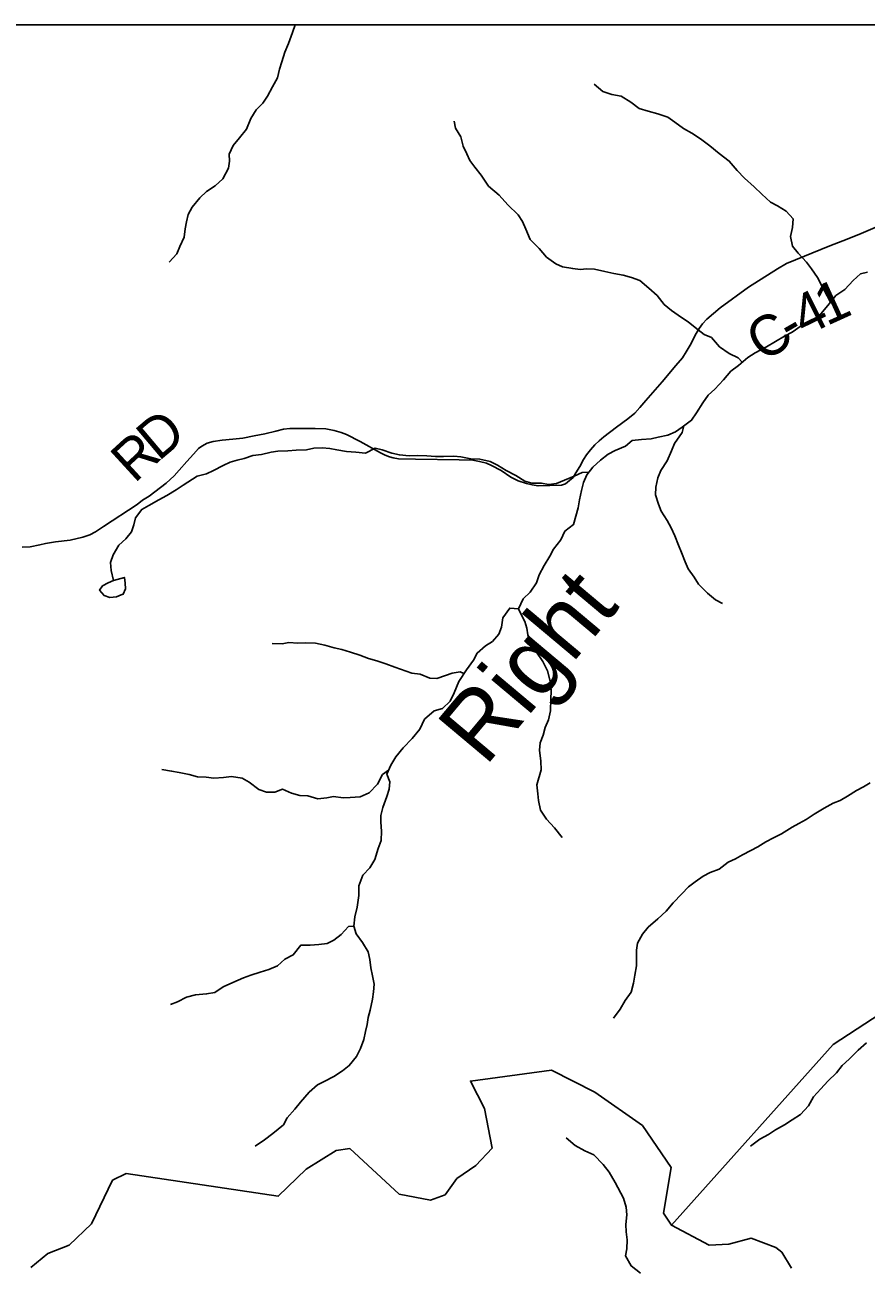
# Model space of a CAD drawing. Extents: x 0 to 34, y 0 to 22.
# Drawn here: x 5.025 to 6.209, y 19.152 to 20.9 of the extents above; entities that cross this region are included whole.
import ezdxf

# ---------------------------------------------------------------- set-up
doc = ezdxf.new("R2010")
doc.units = 0
for name, color, linetype in [('Default', 7, 'Continuous'), ('GM_X_County_Road', 7, 'Continuous'), ('GM_X_County_Road_Text', 7, 'Continuous'), ('GM_X_Minor_Lake', 7, 'Continuous'), ('GM_X_Minor_River', 7, 'Continuous'), ('GM_X_Minor_River_Text', 7, 'Continuous'), ('SH_Cut_Line', 7, 'Continuous'), ('SH_Data', 7, 'Continuous')]:
    doc.layers.add(name, color=color, linetype=linetype)

msp = doc.modelspace()

# ---------------------------------------------------------------- linework, layer by layer
at = {"layer": 'Default'}
for points in [[(6.416, 20.9), (2.4845, 20.9)], [(8.9, 18.9397), (8.9, 20.9), (6.416, 20.9), (6.3907, 20.8258), (6.4542, 20.7247), (6.5744, 20.5412), (6.467, 20.1963), (6.4168, 20.1498), (6.3788, 19.8553), (6.4211, 19.7542), (6.3989, 19.6679), (6.4166, 19.6301), (6.1627, 19.4643), (5.935, 19.2098), (5.9881, 19.1818), (6.0158, 19.1833), (6.0473, 19.1917), (6.082, 19.1783), (6.0902, 19.1718), (6.104, 19.1492)], [(5.0333, 19.1501), (5.0571, 19.1699), (5.0871, 19.1817), (5.1189, 19.2117), (5.1485, 19.2732), (5.1675, 19.2824), (5.3815, 19.2505), (5.4209, 19.2887), (5.4629, 19.3148), (5.4823, 19.3176), (5.5519, 19.2533), (5.5958, 19.2452), (5.6163, 19.2525), (5.6329, 19.2758), (5.6596, 19.2941), (5.6826, 19.3181), (5.6719, 19.3741), (5.6519, 19.4127), (5.7661, 19.4283), (5.8271, 19.3972), (5.8943, 19.35), (5.9345, 19.291), (5.9239, 19.227), (5.935, 19.2098), (6.1627, 19.4643), (6.4166, 19.6301)], [(6.104, 19.1492), (6.0902, 19.1718), (6.082, 19.1783), (6.0473, 19.1917), (6.0158, 19.1833), (5.9881, 19.1818), (5.935, 19.2098), (5.9239, 19.227), (5.9345, 19.291), (5.8943, 19.35), (5.8271, 19.3972), (5.7661, 19.4283), (5.6519, 19.4127), (5.6719, 19.3741), (5.6826, 19.3181), (5.6596, 19.2941), (5.6329, 19.2758), (5.6163, 19.2525), (5.5958, 19.2452), (5.5519, 19.2533), (5.4823, 19.3176), (5.4629, 19.3148), (5.4209, 19.2887), (5.3815, 19.2505), (5.1675, 19.2824), (5.1485, 19.2732), (5.1189, 19.2117), (5.0871, 19.1817), (5.0571, 19.1699), (5.0333, 19.1501)]]:
    msp.add_lwpolyline(points, dxfattribs=at)
at = {"layer": 'GM_X_County_Road'}
msp.add_lwpolyline([(5.0212, 20.1644), (5.0322, 20.165), (5.0459, 20.168), (5.054, 20.1698), (5.068, 20.1721), (5.0886, 20.1746), (5.1067, 20.1784), (5.1163, 20.1817), (5.1242, 20.1863), (5.1354, 20.1937), (5.183, 20.2247), (5.1906, 20.2306), (5.2, 20.2362), (5.2239, 20.2547), (5.2351, 20.2652), (5.242, 20.273), (5.2527, 20.2853), (5.2621, 20.2957), (5.2692, 20.3033), (5.2738, 20.3066), (5.2814, 20.3109), (5.2898, 20.3135), (5.3025, 20.3153), (5.3175, 20.3165), (5.3315, 20.3181), (5.3475, 20.3211), (5.3625, 20.3239), (5.378, 20.328), (5.389, 20.3305), (5.3979, 20.3318), (5.4134, 20.3315), (5.4337, 20.3318), (5.4485, 20.331), (5.4604, 20.329), (5.4699, 20.3262), (5.4777, 20.3231), (5.4968, 20.3132), (5.5256, 20.2972), (5.5322, 20.2942), (5.538, 20.2919), (5.5431, 20.2903), (5.5507, 20.2891), (5.5749, 20.2883), (5.6364, 20.2875), (5.6553, 20.2868), (5.6649, 20.2853), (5.6748, 20.2827), (5.6817, 20.2797), (5.6952, 20.2723), (5.7087, 20.2631), (5.7193, 20.2578), (5.7308, 20.254), (5.7387, 20.2524), (5.7473, 20.2507), (5.7801, 20.2517), (5.786, 20.2537), (5.7913, 20.2585), (5.7964, 20.2624), (5.8005, 20.269), (5.8058, 20.2781), (5.8112, 20.288), (5.8155, 20.2947), (5.8211, 20.3018), (5.8272, 20.3086), (5.833, 20.3142), (5.8399, 20.3201), (5.8574, 20.3333), (5.8735, 20.345), (5.8834, 20.3534), (5.8905, 20.3613), (5.8989, 20.371), (5.922, 20.3974), (5.9411, 20.4203), (5.9503, 20.431), (5.9556, 20.4396), (5.9625, 20.4513), (5.9683, 20.463), (5.9739, 20.4722), (5.9788, 20.479), (5.9849, 20.4857), (6.0034, 20.5014), (6.0434, 20.5304), (6.0843, 20.5564), (6.097, 20.564), (6.1579, 20.5888), (6.1825, 20.5981), (6.2018, 20.6062), (6.2468, 20.6255)], dxfattribs=at)
at = {"layer": 'GM_X_Minor_Lake'}
for points in [[(5.1603, 20.0972), (5.1634, 20.0984), (5.1665, 20.106), (5.1662, 20.1139), (5.1651, 20.1219), (5.1499, 20.1175)], [(5.1499, 20.1175), (5.142, 20.1141), (5.1343, 20.11), (5.1301, 20.104), (5.1365, 20.0963), (5.1444, 20.0936), (5.1539, 20.0947), (5.1603, 20.0972)]]:
    msp.add_lwpolyline(points, dxfattribs=at)
at = {"layer": 'GM_X_Minor_River'}
for points in [[(5.4055, 20.9), (5.4014, 20.889), (5.396, 20.8738), (5.3909, 20.8614), (5.3867, 20.8477), (5.3832, 20.8375), (5.3804, 20.8254), (5.3735, 20.8126), (5.3666, 20.7994), (5.36, 20.7895), (5.3505, 20.7805), (5.3432, 20.7681), (5.337, 20.7533), (5.3271, 20.7409), (5.3183, 20.7303), (5.3125, 20.7179), (5.3128, 20.708), (5.3116, 20.6981), (5.3035, 20.683), (5.2928, 20.6732)], [(6.1588, 20.5096), (6.154, 20.5185), (6.1473, 20.5315), (6.1406, 20.5441), (6.132, 20.5563), (6.1249, 20.5658), (6.1132, 20.5784), (6.1054, 20.5884), (6.1024, 20.602), (6.1052, 20.6145), (6.1064, 20.6267), (6.0963, 20.6374), (6.0843, 20.6451), (6.0744, 20.6501), (6.0621, 20.6616), (6.0515, 20.6719), (6.0376, 20.6842), (6.0275, 20.6949), (6.0163, 20.7082), (6.0023, 20.719), (5.9888, 20.7297), (5.976, 20.7393), (5.9636, 20.7474), (5.9519, 20.7539), (5.9399, 20.7631), (5.9301, 20.77), (5.9157, 20.7747), (5.9021, 20.7782), (5.8897, 20.7821), (5.8776, 20.7913), (5.8641, 20.7994), (5.8512, 20.8018), (5.8384, 20.8061), (5.8263, 20.8164)], [(6.0346, 20.4249), (6.0287, 20.4312), (6.0162, 20.4373), (6.0027, 20.4466), (5.9911, 20.4596), (5.9809, 20.4642), (5.9685, 20.4738), (5.9587, 20.4818), (5.9489, 20.488), (5.935, 20.4976), (5.9248, 20.506), (5.9147, 20.519), (5.9031, 20.5293), (5.8903, 20.5401), (5.8786, 20.5443), (5.8669, 20.5475), (5.854, 20.5499), (5.8412, 20.5526), (5.8268, 20.5558), (5.8158, 20.5562), (5.8063, 20.5556), (5.7961, 20.5568), (5.7818, 20.5592), (5.772, 20.5634), (5.7592, 20.573), (5.749, 20.5849), (5.7359, 20.5979), (5.73, 20.6123), (5.7255, 20.623), (5.7192, 20.6325), (5.7045, 20.6467), (5.6925, 20.6601), (5.6775, 20.6727), (5.667, 20.6884), (5.658, 20.6994), (5.6513, 20.709), (5.6468, 20.7185), (5.642, 20.7292), (5.6383, 20.7421), (5.6312, 20.7547), (5.629, 20.7642)], [(5.2928, 20.6732), (5.2806, 20.6654), (5.2711, 20.6564), (5.2604, 20.6432), (5.255, 20.633), (5.2526, 20.6227), (5.2506, 20.6129), (5.249, 20.6008), (5.2429, 20.5879), (5.2386, 20.5777), (5.2279, 20.5657)], [(6.2111, 20.5518), (6.2012, 20.5493), (6.1909, 20.5399), (6.1791, 20.5274), (6.1661, 20.5188), (6.155, 20.5049), (6.1451, 20.4932), (6.131, 20.4815), (6.1177, 20.476), (6.1047, 20.4673), (6.0941, 20.4614), (6.0815, 20.4543), (6.0686, 20.4468), (6.0526, 20.4382), (6.0423, 20.4318), (6.0293, 20.4202), (6.0187, 20.4123), (6.008, 20.4002), (5.9961, 20.3871), (5.9866, 20.3784), (5.9793, 20.3678), (5.9701, 20.3535), (5.9632, 20.3433), (5.9502, 20.3336), (5.9407, 20.3268), (5.9301, 20.3223), (5.9161, 20.3194), (5.9066, 20.3172), (5.8929, 20.3162), (5.8797, 20.3148), (5.8701, 20.3069), (5.8557, 20.3006), (5.8458, 20.2957), (5.8351, 20.2871), (5.8244, 20.2773), (5.816, 20.2664), (5.811, 20.2558), (5.8083, 20.2441), (5.8055, 20.2312), (5.8035, 20.2198), (5.8004, 20.2081), (5.7969, 20.1964), (5.7851, 20.187), (5.7793, 20.1749), (5.769, 20.1617), (5.7636, 20.1519), (5.7559, 20.1386), (5.749, 20.1254), (5.7451, 20.1141), (5.7363, 20.1012), (5.7263, 20.0918), (5.7198, 20.0779), (5.7073, 20.0787), (5.6977, 20.0651), (5.6957, 20.0519), (5.6922, 20.042), (5.6831, 20.0319), (5.6732, 20.0255), (5.6617, 20.0154), (5.6563, 20.0052), (5.6464, 19.992), (5.6356, 19.9754), (5.6291, 19.9595), (5.6237, 19.9478), (5.6126, 19.9372), (5.6012, 19.9343), (5.5875, 19.9223), (5.5806, 19.9083)], [(5.9526, 20.3353), (5.9502, 20.326), (5.9391, 20.3105), (5.9352, 20.3003), (5.929, 20.2863), (5.9198, 20.2727), (5.9156, 20.2621), (5.9132, 20.2489), (5.9127, 20.2383), (5.9168, 20.2253), (5.9205, 20.2154), (5.9291, 20.2021), (5.9347, 20.1918), (5.9399, 20.1804), (5.9451, 20.1674), (5.9491, 20.1572), (5.9543, 20.1438), (5.9584, 20.1339), (5.967, 20.1225), (5.973, 20.1126), (5.9858, 20.0999), (5.997, 20.0904), (6.0068, 20.085)], [(5.8188, 20.2699), (5.8092, 20.2695), (5.7982, 20.2646), (5.7842, 20.2591), (5.7731, 20.2542), (5.7622, 20.2528), (5.7516, 20.2548), (5.7383, 20.2545), (5.7285, 20.2576), (5.7161, 20.2653), (5.7025, 20.2723), (5.6901, 20.2799), (5.6799, 20.2853), (5.6652, 20.2885), (5.6527, 20.289), (5.6387, 20.2917), (5.6285, 20.2926), (5.6141, 20.2923), (5.6031, 20.292), (5.5906, 20.2929), (5.5781, 20.2934), (5.566, 20.2931), (5.552, 20.2944), (5.5414, 20.2971), (5.5278, 20.3014), (5.518, 20.3038), (5.5043, 20.2967), (5.4907, 20.2983), (5.4778, 20.2992), (5.4642, 20.3015), (5.454, 20.3035), (5.4434, 20.3044), (5.4317, 20.3037), (5.4211, 20.3015), (5.407, 20.3009), (5.3949, 20.3002), (5.3809, 20.2996), (5.3714, 20.2981), (5.3578, 20.2952), (5.346, 20.2938), (5.3335, 20.2893), (5.3236, 20.2871), (5.3138, 20.2842), (5.3039, 20.2797), (5.2906, 20.2726), (5.2807, 20.2678), (5.2674, 20.2645), (5.2476, 20.2517), (5.2381, 20.2454), (5.2248, 20.2375), (5.2137, 20.2311), (5.1993, 20.2233), (5.1894, 20.2177), (5.1806, 20.2056), (5.1782, 20.1958), (5.1751, 20.1859), (5.1671, 20.1761), (5.1572, 20.1675), (5.1491, 20.1535), (5.1456, 20.1429), (5.1466, 20.1315), (5.1499, 20.1175)], [(5.7198, 20.0779), (5.7235, 20.0695), (5.7287, 20.06), (5.7313, 20.0504), (5.7327, 20.041), (5.7361, 20.0303), (5.7439, 20.0181), (5.754, 20.0036), (5.7603, 19.9903), (5.7647, 19.9739), (5.7658, 19.9618), (5.7653, 19.9508), (5.7648, 19.9341), (5.762, 19.9212), (5.757, 19.9106), (5.7543, 19.8996), (5.75, 19.889), (5.7492, 19.8788), (5.7509, 19.8632), (5.7516, 19.8511), (5.7453, 19.8299), (5.7468, 19.8174), (5.7478, 19.8079), (5.7507, 19.7942), (5.7593, 19.7816), (5.7702, 19.7694), (5.7811, 19.7556)], [(5.6429, 19.9867), (5.6376, 19.989), (5.6263, 19.9872), (5.6168, 19.9839), (5.6046, 19.9794), (5.5948, 19.9803), (5.5812, 19.9857), (5.5695, 19.9873), (5.5457, 19.9955), (5.5332, 20.0001), (5.5204, 20.0044), (5.5087, 20.0079), (5.4962, 20.0126), (5.4834, 20.0168), (5.4709, 20.0204), (5.4604, 20.0227), (5.4471, 20.0266), (5.4339, 20.0294), (5.4195, 20.0299), (5.4093, 20.0292), (5.3964, 20.0301), (5.387, 20.0283), (5.3729, 20.0288)], [(5.5806, 19.9083), (5.5702, 19.8951), (5.5572, 19.8819), (5.5469, 19.8691), (5.54, 19.8574), (5.5342, 19.8449), (5.5387, 19.8343), (5.5378, 19.8236), (5.5343, 19.8134), (5.5289, 19.7979), (5.5261, 19.7866), (5.5257, 19.7771), (5.5271, 19.7646), (5.5266, 19.7513), (5.522, 19.7403), (5.5177, 19.7248), (5.5104, 19.7131), (5.5008, 19.7029), (5.495, 19.6878), (5.4949, 19.6741), (5.4925, 19.6575), (5.4894, 19.6438), (5.4877, 19.631), (5.4911, 19.6203), (5.5, 19.6077), (5.5083, 19.5947), (5.5104, 19.5841), (5.5119, 19.5723), (5.514, 19.5609), (5.5166, 19.5491), (5.5157, 19.5385), (5.5141, 19.5279), (5.511, 19.5128), (5.5079, 19.5025), (5.5066, 19.4923), (5.5043, 19.4825), (5.5019, 19.4715), (5.4973, 19.4586), (5.4919, 19.4473), (5.4815, 19.4345), (5.472, 19.427), (5.4598, 19.4191), (5.4461, 19.4124), (5.4366, 19.4075), (5.4252, 19.397), (5.413, 19.3831), (5.4049, 19.3733), (5.3942, 19.3608), (5.3888, 19.351), (5.374, 19.339), (5.3622, 19.33), (5.3492, 19.321)], [(5.5367, 19.8504), (5.5285, 19.8442), (5.5212, 19.831), (5.5094, 19.8186), (5.4968, 19.813), (5.4828, 19.812), (5.473, 19.8117), (5.4594, 19.8133), (5.4499, 19.8115), (5.4374, 19.8101), (5.423, 19.8144), (5.4117, 19.8148), (5.4003, 19.818), (5.3875, 19.8238), (5.3769, 19.8197), (5.3648, 19.8194), (5.3542, 19.8233), (5.3406, 19.8336), (5.3308, 19.8394), (5.3157, 19.8418), (5.3047, 19.8404), (5.2911, 19.8393), (5.2801, 19.8406), (5.268, 19.8411), (5.2563, 19.8442), (5.2419, 19.8473), (5.2314, 19.8493), (5.2177, 19.8517)], [(6.2148, 19.8325), (6.2053, 19.8269), (6.1955, 19.822), (6.1829, 19.8138), (6.1726, 19.8078), (6.1627, 19.8041), (6.1498, 19.797), (6.1357, 19.7887), (6.1247, 19.7812), (6.1144, 19.7753), (6.1049, 19.7704), (6.0897, 19.761), (6.0787, 19.7554), (6.068, 19.7495), (6.0566, 19.7427), (6.0467, 19.7375), (6.0349, 19.7315), (6.025, 19.7255), (6.0148, 19.7211), (6.0022, 19.7113), (5.9893, 19.7065), (5.9794, 19.7012), (5.9683, 19.6934), (5.9588, 19.6862), (5.9496, 19.6765), (5.9374, 19.6637), (5.9275, 19.652), (5.916, 19.6411), (5.9023, 19.6294), (5.8943, 19.6196), (5.8873, 19.6068), (5.8857, 19.5969), (5.886, 19.5852), (5.8856, 19.5749), (5.8836, 19.562), (5.8816, 19.5507), (5.8781, 19.5378), (5.87, 19.5261), (5.8627, 19.514), (5.8535, 19.5012)], [(5.4878, 19.6311), (5.4805, 19.6303), (5.4702, 19.619), (5.4599, 19.6111), (5.4504, 19.6066), (5.4387, 19.6052), (5.4266, 19.6041), (5.4133, 19.6039), (5.4026, 19.5903), (5.3908, 19.5843), (5.3805, 19.5749), (5.3683, 19.5697), (5.3562, 19.566), (5.3429, 19.562), (5.3326, 19.5579), (5.3178, 19.5515), (5.3038, 19.5456), (5.2923, 19.5377), (5.2806, 19.5355), (5.2651, 19.5341), (5.2522, 19.5308), (5.2396, 19.5245), (5.2297, 19.5204)], [(6.2095, 19.4668), (6.1977, 19.4563), (6.1851, 19.4438), (6.1752, 19.4348), (6.1671, 19.4246), (6.1549, 19.4126), (6.1454, 19.402), (6.135, 19.3908), (6.1277, 19.3779), (6.1167, 19.3655), (6.1049, 19.3584), (6.0942, 19.3513), (6.0816, 19.3441), (6.0714, 19.3374), (6.0592, 19.3311), (6.0462, 19.3209)], [(5.8915, 19.1425), (5.8783, 19.1524), (5.8704, 19.1665), (5.872, 19.1764), (5.8725, 19.1893), (5.8714, 19.2007), (5.8707, 19.2106), (5.8723, 19.2243), (5.8713, 19.2353), (5.8676, 19.2478), (5.8556, 19.2699), (5.8473, 19.2844), (5.8387, 19.2951), (5.8255, 19.3089), (5.813, 19.3147), (5.7994, 19.322), (5.7866, 19.3327)]]:
    msp.add_lwpolyline(points, dxfattribs=at)
at = {"layer": 'SH_Cut_Line'}
msp.add_lwpolyline([(2.4352, 14.1), (8.9, 14.1), (8.9, 20.9), (2.4845, 20.9), (2.4809, 20.6393), (2.4757, 20.2566), (2.4573, 18.9074), (2.4581, 18.1825), (2.4581, 18.1772), (2.4586, 17.7785), (2.4545, 17.2795), (2.4313, 15.0183), (2.4372, 14.2719)], close=True, dxfattribs=at)
at = {"layer": 'SH_Data'}
msp.add_line((2.1, 20.9), (8.9, 20.9), dxfattribs=at)

# ---------------------------------------------------------------- texts
at = {"layer": 'GM_X_County_Road_Text'}
for s, rotation, p in [('1', 24.4852, (6.1533, 20.4756)), ('4', 26.2857, (6.1224, 20.4603)), ('C', 33.4877, (6.0649, 20.4239)), ('-', 29.8867, (6.103, 20.4491)), ('D', 40.1283, (5.213, 20.2845)), ('R', 42.5016, (5.1791, 20.2534))]:
    msp.add_text(s, height=0.0568, rotation=rotation, dxfattribs=at).set_placement(p)
at = {"layer": 'GM_X_Minor_River_Text'}
msp.add_text('Right', height=0.0947, rotation=50.0017, dxfattribs=at).set_placement((5.673, 19.8544))

doc.saveas('drawing.dxf')
